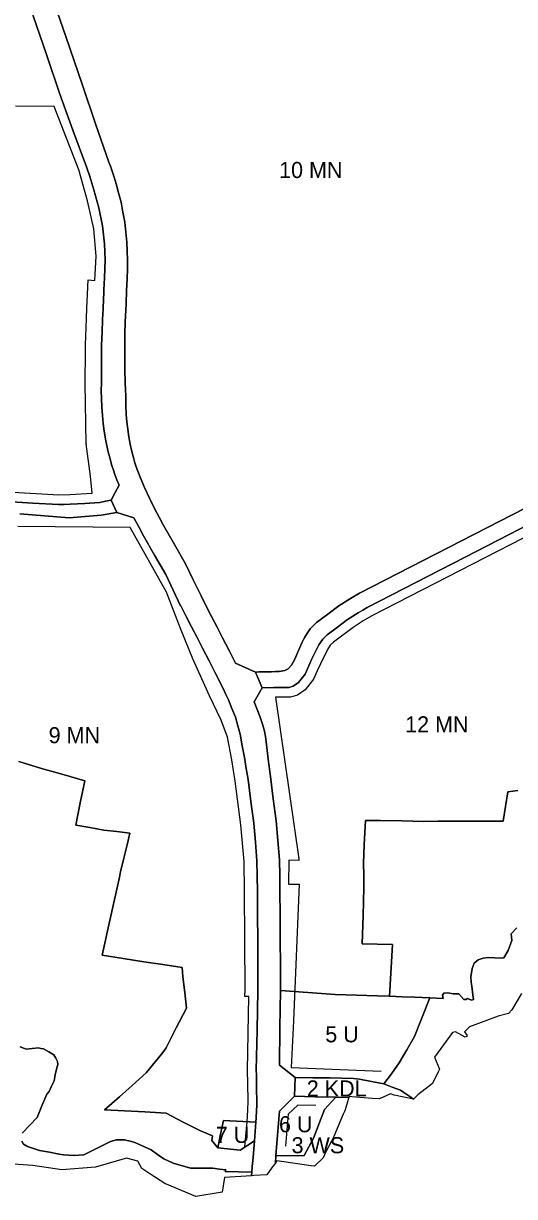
# Model space of a CAD drawing. Extents: x -294445 to -292055, y 21869 to 23693.
# Drawn here: x -293575 to -293270, y 21869 to 22598 of the extents above; entities that cross this region are included whole.
import ezdxf

# ---------------------------------------------------------------- set-up
doc = ezdxf.new("R2010")
doc.units = 0
for name, color, linetype in [('linie_rozgraniczajace', 7, 'Continuous'), ('linie_zabudowy_nieprzekraczalne', 7, 'Continuous'), ('oznaczenia_przeznaczen', 7, 'Continuous')]:
    doc.layers.add(name, color=color, linetype=linetype)

msp = doc.modelspace()

# ---------------------------------------------------------------- linework, layer by layer
at = {"layer": 'linie_rozgraniczajace'}
for points in [[(-293577.87, 22637.216), (-293574.744, 22625.222), (-293571.617, 22613.228), (-293570.297, 22608.174), (-293568.976, 22603.119), (-293560.739, 22579.011), (-293552.502, 22554.903), (-293544.186, 22532.017), (-293535.87, 22509.13), (-293533.775, 22503.209), (-293532.496, 22499.067), (-293531.216, 22494.926), (-293528.188, 22483.748), (-293525.773, 22472.607), (-293525.217, 22466.971), (-293524.661, 22461.334), (-293524.437, 22456.329), (-293524.213, 22451.323), (-293524.389, 22445.81)], [(-293461.287, 22236.143), (-293464.591, 22242.61), (-293469.372, 22252.502), (-293474.154, 22262.394), (-293481.129, 22274.51), (-293488.104, 22286.625), (-293490.691, 22291.51), (-293493.279, 22296.396), (-293496.551, 22303.171), (-293499.824, 22309.945), (-293502.409, 22316.346), (-293504.994, 22322.748), (-293505.715, 22325.192), (-293506.436, 22327.637), (-293507.531, 22332.178), (-293508.625, 22336.72), (-293509.395, 22341.445), (-293510.164, 22346.169), (-293510.605, 22350.692), (-293511.045, 22355.215), (-293511.223, 22360.983), (-293511.4, 22366.75), (-293511.555, 22370.709), (-293511.711, 22374.668), (-293511.865, 22383.437), (-293512.02, 22392.206), (-293511.995, 22395.019), (-293511.97, 22397.833), (-293511.932, 22401.583), (-293511.893, 22405.333), (-293511.641, 22412.706), (-293511.39, 22420.08), (-293511.116, 22424.28), (-293510.844, 22432.055), (-293510.573, 22439.83), (-293510.388, 22445.621), (-293510.203, 22451.413), (-293510.447, 22456.874), (-293510.692, 22462.335), (-293511.306, 22468.56), (-293511.92, 22474.784), (-293513.104, 22481.003), (-293514.288, 22487.223), (-293515.822, 22492.932), (-293517.357, 22498.642), (-293518.653, 22502.848), (-293519.95, 22507.054), (-293520.885, 22509.542), (-293521.819, 22512.029), (-293530.087, 22535.959), (-293538.354, 22559.89), (-293548.673, 22590.091), (-293558.985, 22620.268)], [(-293558.985, 22620.268), (-293548.673, 22590.091), (-293538.354, 22559.89), (-293530.087, 22535.959), (-293521.819, 22512.029), (-293520.885, 22509.542), (-293519.95, 22507.054), (-293518.653, 22502.848), (-293517.357, 22498.642), (-293515.822, 22492.932), (-293514.288, 22487.223), (-293513.104, 22481.003), (-293511.92, 22474.784), (-293511.306, 22468.56), (-293510.692, 22462.335), (-293510.447, 22456.874), (-293510.203, 22451.413), (-293510.388, 22445.621), (-293510.573, 22439.83), (-293510.844, 22432.055), (-293511.116, 22424.28), (-293511.39, 22420.08), (-293511.641, 22412.706), (-293511.893, 22405.333), (-293511.932, 22401.583), (-293511.97, 22397.833), (-293511.995, 22395.019)], [(-293447.498, 22178.015), (-293449.078, 22181.306), (-293450.657, 22184.597), (-293451.761, 22186.812), (-293452.865, 22189.027), (-293455.577, 22194.311), (-293459.618, 22202.184), (-293463.659, 22210.057), (-293467.052, 22216.678), (-293470.446, 22223.298), (-293473.752, 22229.769), (-293477.058, 22236.241), (-293477.252, 22236.381), (-293481.904, 22246.129), (-293486.556, 22255.877), (-293493.458, 22267.866), (-293500.36, 22279.854), (-293503.066, 22284.963), (-293506.251, 22291.065), (-293516.857, 22294.294), (-293520.418, 22302.027), (-293517.972, 22306.732), (-293515.525, 22311.438), (-293516.829, 22314.665), (-293518.132, 22317.893), (-293519.088, 22320.737), (-293520.043, 22323.581), (-293521.324, 22328.233), (-293522.604, 22332.885), (-293523.694, 22338.843), (-293524.784, 22344.8), (-293525.323, 22349.679), (-293525.861, 22354.558), (-293526.22, 22360.124), (-293526.557, 22370.219), (-293526.533, 22374.748), (-293526.482, 22384.564), (-293526.43, 22394.38), (-293526.4, 22398.38), (-293526.095, 22406.38), (-293525.79, 22414.38), (-293525.507, 22421.006), (-293525.401, 22423.003), (-293525.294, 22425), (-293524.93, 22432.649), (-293524.565, 22440.297), (-293524.389, 22445.81), (-293524.213, 22451.323), (-293524.437, 22456.329), (-293524.661, 22461.334), (-293525.217, 22466.971), (-293525.773, 22472.607), (-293528.188, 22483.748), (-293531.216, 22494.926), (-293532.496, 22499.067), (-293533.775, 22503.209), (-293535.87, 22509.13), (-293544.186, 22532.017), (-293552.502, 22554.903), (-293560.739, 22579.011), (-293568.976, 22603.119)], [(-293524.389, 22445.81), (-293524.565, 22440.297), (-293524.93, 22432.649), (-293525.294, 22425), (-293525.401, 22423.003), (-293525.507, 22421.006), (-293525.79, 22414.38), (-293526.095, 22406.38), (-293526.4, 22398.38), (-293526.43, 22394.38), (-293526.482, 22384.564), (-293526.533, 22374.748), (-293526.557, 22370.219), (-293526.22, 22360.124), (-293525.861, 22354.558), (-293525.323, 22349.679), (-293524.784, 22344.8), (-293523.694, 22338.843), (-293522.604, 22332.885), (-293521.324, 22328.233), (-293520.043, 22323.581), (-293519.088, 22320.737), (-293518.132, 22317.893), (-293516.829, 22314.665), (-293515.525, 22311.438), (-293517.972, 22306.732), (-293520.418, 22302.027), (-293523.989, 22301.308), (-293527.56, 22300.59), (-293536.775, 22300.015), (-293545.99, 22299.44), (-293549.595, 22299.39), (-293553.2, 22299.34), (-293569.2, 22300.225), (-293585.2, 22301.11)], [(-293511.995, 22395.019), (-293512.02, 22392.206), (-293511.865, 22383.437), (-293511.711, 22374.668), (-293511.555, 22370.709), (-293511.4, 22366.75), (-293511.223, 22360.983), (-293511.045, 22355.215), (-293510.605, 22350.692), (-293510.164, 22346.169), (-293509.395, 22341.445), (-293508.625, 22336.72), (-293507.531, 22332.178), (-293506.436, 22327.637), (-293505.715, 22325.192), (-293504.994, 22322.748), (-293502.409, 22316.346), (-293499.824, 22309.945), (-293496.551, 22303.171), (-293493.279, 22296.396), (-293490.691, 22291.51), (-293488.104, 22286.625), (-293481.129, 22274.51), (-293474.154, 22262.394), (-293469.372, 22252.502), (-293464.591, 22242.61), (-293461.287, 22236.143), (-293457.982, 22229.675), (-293454.591, 22223.059), (-293451.2, 22216.443), (-293447.179, 22208.608), (-293443.158, 22200.773), (-293430.692, 22195.192), (-293426.637, 22185.293), (-293431.464, 22176.658), (-293429.664, 22171.853), (-293427.864, 22167.047), (-293426.447, 22162.709), (-293425.03, 22158.37), (-293424.52, 22155.115), (-293424.01, 22151.86), (-293422.746, 22141.016), (-293421.482, 22130.172), (-293419.671, 22116.421), (-293417.86, 22102.67), (-293416.85, 22090.565), (-293415.84, 22078.46), (-293415.675, 22068.8), (-293415.51, 22059.14), (-293415.44, 22043.96), (-293415.37, 22028.78), (-293415.28, 22013.025), (-293415.19, 21997.27), (-293415.52, 21974.08), (-293415.85, 21950.89), (-293406, 21943.11), (-293406.443, 21931.593), (-293415.877, 21922.232), (-293416.276, 21917.222), (-293416.674, 21912.213), (-293417.457, 21902.341), (-293418.08, 21894.492), (-293418.388, 21890.053), (-293420.31, 21887.39), (-293423.69, 21882.73), (-293431.66, 21882.22), (-293433.299, 21882.115), (-293433.087, 21884.315), (-293432.753, 21887.782), (-293432.206, 21893.448), (-293431.381, 21903.848), (-293430.506, 21915.356), (-293430.343, 21918.043), (-293430.057, 21922.763), (-293429.978, 21925.797), (-293429.9, 21928.83), (-293430.02, 21935.45), (-293430.14, 21942.07), (-293430.195, 21944.945), (-293430.25, 21947.82), (-293429.72, 21972.575), (-293429.191, 21997.33), (-293429.28, 22013.019), (-293429.37, 22028.708), (-293429.44, 22043.848), (-293429.509, 22058.988), (-293429.67, 22068.373), (-293429.83, 22077.758), (-293430.807, 22089.465), (-293431.784, 22101.173), (-293433.58, 22114.81), (-293435.376, 22128.448), (-293436.44, 22135.282), (-293437.504, 22142.116), (-293438.922, 22149.323), (-293440.34, 22156.53), (-293441.76, 22161.825), (-293443.18, 22167.12), (-293445.339, 22172.567), (-293447.498, 22178.015)], [(-293239.368, 22309.206), (-293302.714, 22276.673), (-293366.06, 22244.14), (-293371.586, 22240.965), (-293378.858, 22236.241), (-293385.839, 22231.085), (-293392.82, 22225.929), (-293394.785, 22223.98), (-293396.75, 22222.032), (-293398.428, 22219.484), (-293400.105, 22216.935), (-293400.896, 22215.39), (-293401.686, 22213.845), (-293404.005, 22208.53), (-293406.323, 22203.215), (-293407.359, 22201.348), (-293408.395, 22199.482), (-293410.375, 22197.1), (-293412.577, 22196.212), (-293415.968, 22195.603), (-293418.249, 22195.517), (-293420.753, 22195.422), (-293423.701, 22195.372), (-293426.65, 22195.323), (-293428.671, 22195.257), (-293430.692, 22195.192), (-293443.158, 22200.773), (-293447.179, 22208.608), (-293451.2, 22216.443), (-293454.591, 22223.059), (-293457.982, 22229.675), (-293461.287, 22236.143)], [(-293430.692, 22195.192), (-293428.671, 22195.257), (-293426.65, 22195.323), (-293423.701, 22195.372), (-293420.753, 22195.422), (-293418.249, 22195.517), (-293415.968, 22195.603), (-293412.577, 22196.212), (-293410.375, 22197.1), (-293408.395, 22199.482), (-293407.359, 22201.348), (-293406.323, 22203.215), (-293404.005, 22208.53), (-293401.686, 22213.845), (-293400.896, 22215.39), (-293400.105, 22216.935), (-293398.428, 22219.484), (-293396.75, 22222.032), (-293394.785, 22223.98), (-293392.82, 22225.929), (-293385.839, 22231.085), (-293378.858, 22236.241), (-293371.586, 22240.965), (-293366.06, 22244.14), (-293302.714, 22276.673), (-293239.368, 22309.206)], [(-293585.2, 22301.11), (-293569.2, 22300.225), (-293553.2, 22299.34), (-293549.595, 22299.39), (-293545.99, 22299.44), (-293536.775, 22300.015), (-293527.56, 22300.59), (-293523.989, 22301.308), (-293520.418, 22302.027), (-293516.857, 22294.294), (-293526.67, 22292.75), (-293536.565, 22291.925), (-293546.46, 22291.1), (-293561.8, 22292.265), (-293577.14, 22293.43)], [(-293267.58, 22121.58), (-293270.775, 22121.14), (-293273.97, 22120.7), (-293275.353, 22111.558), (-293276.735, 22102.415), (-293278.559, 22102.424), (-293285.604, 22102.457), (-293292.65, 22102.49), (-293300.55, 22102.525), (-293308.45, 22102.56), (-293317.375, 22102.48), (-293326.3, 22102.4), (-293339.65, 22102.625), (-293353, 22102.85), (-293357.695, 22102.93), (-293362.39, 22103.01), (-293362.576, 22099.187), (-293363.133, 22087.764), (-293363.69, 22076.34), (-293363.485, 22068.795), (-293363.28, 22061.25), (-293363.835, 22043.81), (-293364.39, 22026.37), (-293345.484, 22025.806), (-293347.351, 21993.692), (-293354.9, 21993.94), (-293368.005, 21994.37), (-293381.11, 21994.8), (-293398.15, 21996.035), (-293415.19, 21997.27), (-293415.28, 22013.025), (-293415.37, 22028.78), (-293415.44, 22043.96), (-293415.51, 22059.14), (-293415.675, 22068.8), (-293415.84, 22078.46), (-293416.85, 22090.565), (-293417.86, 22102.67), (-293419.671, 22116.421), (-293421.482, 22130.172), (-293422.746, 22141.016), (-293424.01, 22151.86), (-293424.52, 22155.115), (-293425.03, 22158.37), (-293426.447, 22162.709), (-293427.864, 22167.047), (-293429.664, 22171.853), (-293431.464, 22176.658), (-293426.637, 22185.293), (-293419.288, 22185.5), (-293414.598, 22185.512), (-293409.908, 22185.524), (-293407.28, 22186.34), (-293403.95, 22188.59), (-293399.77, 22193.87), (-293396.863, 22200.588), (-293395.827, 22202.922), (-293393.542, 22207.556), (-293391.257, 22212.19), (-293388.97, 22215.664), (-293386.221, 22218.391), (-293379.84, 22223.114), (-293373.459, 22227.837), (-293370.151, 22229.957), (-293366.843, 22232.077), (-293364.105, 22233.693), (-293361.368, 22235.308), (-293300.311, 22266.665), (-293239.255, 22298.022)], [(-293239.255, 22298.022), (-293300.311, 22266.665), (-293361.368, 22235.308), (-293364.105, 22233.693), (-293366.843, 22232.077), (-293370.151, 22229.957), (-293373.459, 22227.837), (-293379.84, 22223.114), (-293386.221, 22218.391), (-293388.97, 22215.664), (-293391.257, 22212.19), (-293393.542, 22207.556), (-293395.827, 22202.922), (-293396.863, 22200.588), (-293399.77, 22193.87), (-293403.95, 22188.59), (-293407.28, 22186.34), (-293409.908, 22185.524), (-293414.598, 22185.512), (-293419.288, 22185.5), (-293426.637, 22185.293), (-293430.692, 22195.192)], [(-293577.14, 22293.43), (-293561.8, 22292.265), (-293546.46, 22291.1), (-293536.565, 22291.925), (-293526.67, 22292.75), (-293516.857, 22294.294), (-293506.251, 22291.065), (-293503.066, 22284.963), (-293500.36, 22279.854), (-293493.458, 22267.866), (-293486.556, 22255.877), (-293481.904, 22246.129), (-293477.252, 22236.381), (-293477.058, 22236.241), (-293473.752, 22229.769), (-293470.446, 22223.298), (-293467.052, 22216.678), (-293463.659, 22210.057), (-293459.618, 22202.184), (-293455.577, 22194.311), (-293452.865, 22189.027), (-293451.761, 22186.812), (-293450.657, 22184.597), (-293449.078, 22181.306), (-293447.498, 22178.015), (-293445.339, 22172.567), (-293443.18, 22167.12), (-293441.76, 22161.825), (-293440.34, 22156.53), (-293438.922, 22149.323), (-293437.504, 22142.116), (-293436.44, 22135.282), (-293435.376, 22128.448), (-293433.58, 22114.81), (-293431.784, 22101.173), (-293430.807, 22089.465), (-293429.83, 22077.758), (-293429.67, 22068.373), (-293429.509, 22058.988), (-293429.44, 22043.848), (-293429.37, 22028.708), (-293429.28, 22013.019), (-293429.191, 21997.33), (-293429.72, 21972.575), (-293430.25, 21947.82), (-293430.195, 21944.945), (-293430.14, 21942.07), (-293430.02, 21935.45), (-293429.9, 21928.83), (-293429.978, 21925.797), (-293430.057, 21922.763), (-293430.343, 21918.043), (-293430.506, 21915.356), (-293450.571, 21916.441), (-293452.39, 21907.935), (-293454.21, 21899.43), (-293457.97, 21904.02), (-293457.509, 21906.887), (-293464.981, 21910.031), (-293475.662, 21915.48), (-293486.343, 21920.929), (-293499.585, 21921.866), (-293512.071, 21922.457), (-293524.556, 21923.047), (-293519.958, 21927.134), (-293515.36, 21931.221), (-293511.424, 21934.719), (-293507.487, 21938.218), (-293503.081, 21942.133), (-293498.675, 21946.049), (-293493.918, 21951.858), (-293489.161, 21957.667)], [(-293489.161, 21957.667), (-293487.679, 21959.611), (-293486.197, 21961.555), (-293479.942, 21973.967), (-293473.687, 21986.379), (-293474.75, 21996.073), (-293475.812, 22005.768), (-293476.05, 22008.634), (-293476.288, 22011.499), (-293488.234, 22013.34), (-293500.18, 22015.18), (-293513.07, 22017.16), (-293525.96, 22019.14), (-293524.34, 22026.715), (-293522.72, 22034.29), (-293519.625, 22048.25), (-293516.53, 22062.21), (-293515.555, 22066.605), (-293514.58, 22071), (-293512.584, 22079.414), (-293510.588, 22087.828), (-293508.8, 22094.99), (-293516.88, 22095.995), (-293524.96, 22097), (-293533.7, 22098.505), (-293542.44, 22100.01), (-293539.65, 22113.815), (-293536.86, 22127.62), (-293550.27, 22131.455), (-293563.68, 22135.29), (-293577.79, 22139.63)], [(-293577.79, 22139.63), (-293563.68, 22135.29), (-293550.27, 22131.455), (-293536.86, 22127.62), (-293539.65, 22113.815), (-293542.44, 22100.01), (-293533.7, 22098.505), (-293524.96, 22097), (-293516.88, 22095.995), (-293508.8, 22094.99), (-293510.588, 22087.828), (-293512.584, 22079.414), (-293514.58, 22071), (-293515.555, 22066.605), (-293516.53, 22062.21), (-293519.625, 22048.25), (-293522.72, 22034.29), (-293524.34, 22026.715), (-293525.96, 22019.14), (-293513.07, 22017.16), (-293500.18, 22015.18), (-293488.234, 22013.34), (-293476.288, 22011.499), (-293476.05, 22008.634), (-293475.812, 22005.768), (-293474.75, 21996.073), (-293473.687, 21986.379), (-293479.942, 21973.967), (-293486.197, 21961.555), (-293487.679, 21959.611), (-293489.161, 21957.667), (-293493.918, 21951.858), (-293498.675, 21946.049), (-293503.081, 21942.133), (-293507.487, 21938.218), (-293511.424, 21934.719), (-293515.36, 21931.221), (-293519.958, 21927.134), (-293524.556, 21923.047), (-293512.071, 21922.457), (-293499.585, 21921.866), (-293486.343, 21920.929), (-293475.662, 21915.48), (-293464.981, 21910.031), (-293457.509, 21906.887), (-293457.97, 21904.02), (-293454.21, 21899.43), (-293440.302, 21898.099), (-293431.381, 21903.848), (-293432.206, 21893.448), (-293432.753, 21887.782), (-293433.087, 21884.315), (-293449.51, 21884.67), (-293449.08, 21885.78), (-293453.18, 21886.295), (-293457.28, 21886.81), (-293464.24, 21886.82), (-293471.2, 21886.83), (-293481.878, 21889.943), (-293487.64, 21892.55), (-293491.615, 21895.355), (-293495.59, 21898.16), (-293499.72, 21900.115), (-293503.85, 21902.07), (-293505.795, 21902.745), (-293507.74, 21903.42), (-293512.12, 21904.39), (-293517.14, 21904.42), (-293520.76, 21903.34), (-293529.075, 21899.205), (-293537.39, 21895.07), (-293540.465, 21894.875), (-293543.54, 21894.68), (-293546.835, 21894.915), (-293550.13, 21895.15), (-293552.84, 21895.6), (-293558.87, 21896.76), (-293564.9, 21897.92), (-293568.685, 21899.145), (-293572.47, 21900.37), (-293574.85, 21901.66), (-293575.88, 21903.54)], [(-293364.39, 22026.37), (-293363.835, 22043.81), (-293363.28, 22061.25), (-293363.485, 22068.795), (-293363.69, 22076.34), (-293363.133, 22087.764), (-293362.576, 22099.187), (-293362.39, 22103.01), (-293357.695, 22102.93), (-293353, 22102.85), (-293339.65, 22102.625), (-293326.3, 22102.4), (-293317.375, 22102.48), (-293308.45, 22102.56), (-293300.55, 22102.525), (-293292.65, 22102.49), (-293285.604, 22102.457), (-293278.559, 22102.424), (-293276.735, 22102.415), (-293275.353, 22111.558), (-293273.97, 22120.7), (-293270.775, 22121.14), (-293267.58, 22121.58)], [(-293268.31, 22036.13), (-293271.88, 22032.42), (-293271.39, 22028.43), (-293273.69, 22022.1), (-293276.417, 22017.468), (-293277.732, 22017.303), (-293281.947, 22017.504), (-293286.162, 22017.705), (-293289.19, 22017.3), (-293292.28, 22016.41), (-293294.71, 22014.29), (-293296.1, 22010.98), (-293296.83, 22005.66), (-293296.57, 22002.53), (-293296.24, 22000), (-293295.55, 21994.65), (-293295.24, 21991.76), (-293296.52, 21991.19), (-293298.87, 21992.34), (-293299.99, 21991.66), (-293301.14, 21991.58), (-293304.24, 21995.26), (-293307.77, 21995.28), (-293311.1, 21995.9), (-293313.55, 21995.53), (-293314.48, 21994.29), (-293314.05, 21992.23), (-293322.43, 21992.67), (-293327.138, 21992.865), (-293331.846, 21993.06), (-293339.598, 21993.376), (-293347.351, 21993.692), (-293345.484, 22025.806), (-293364.39, 22026.37)], [(-293350.95, 21939.18), (-293346.285, 21945.551), (-293341.41, 21952.21), (-293336.7, 21960.42), (-293331.99, 21968.63), (-293327.993, 21978.682), (-293322.43, 21992.67), (-293314.05, 21992.23), (-293314.48, 21994.29), (-293313.55, 21995.53), (-293311.1, 21995.9), (-293307.77, 21995.28), (-293304.24, 21995.26), (-293301.14, 21991.58), (-293299.99, 21991.66), (-293298.87, 21992.34), (-293296.52, 21991.19), (-293295.24, 21991.76), (-293295.55, 21994.65), (-293296.24, 22000), (-293296.57, 22002.53), (-293296.83, 22005.66), (-293296.1, 22010.98), (-293294.71, 22014.29), (-293292.28, 22016.41), (-293289.19, 22017.3), (-293286.162, 22017.705), (-293281.947, 22017.504), (-293277.732, 22017.303), (-293276.417, 22017.468), (-293273.69, 22022.1), (-293271.39, 22028.43), (-293271.88, 22032.42), (-293268.31, 22036.13)], [(-293265.33, 21995.34), (-293271.48, 21985.26), (-293273.51, 21983), (-293279.94, 21981.29), (-293297.75, 21974.6), (-293300.77, 21971.67), (-293299.13, 21969.29), (-293299.59, 21968.7), (-293300.42, 21968.34), (-293306.34, 21971.65), (-293308.36, 21971.25), (-293319.55, 21955.9), (-293316.28, 21948.43), (-293316.94, 21947.1), (-293320.69, 21939.54), (-293329.88, 21932.43), (-293332.49, 21929.81), (-293334.76, 21931.337), (-293338.493, 21933.848), (-293340.568, 21935.244), (-293345.76, 21937.213), (-293350.95, 21939.18)], [(-293575.67, 21908.57), (-293571.085, 21913.48), (-293566.5, 21918.39), (-293563.495, 21925.645), (-293560.49, 21932.9), (-293559.04, 21934.45), (-293557.49, 21937.78), (-293555.94, 21941.11), (-293555.21, 21944.785), (-293554.48, 21948.46), (-293554.015, 21949.84), (-293553.55, 21951.22), (-293553.84, 21953.23), (-293554.91, 21955.25), (-293555.98, 21957.27), (-293559.225, 21959.14), (-293562.47, 21961.01), (-293564.09, 21961.29), (-293565.71, 21961.57), (-293569.47, 21961.175), (-293573.23, 21960.78), (-293577.04, 21962.265)], [(-293577.04, 21962.265), (-293573.23, 21960.78), (-293569.47, 21961.175), (-293565.71, 21961.57), (-293564.09, 21961.29), (-293562.47, 21961.01), (-293559.225, 21959.14), (-293555.98, 21957.27), (-293554.91, 21955.25), (-293553.84, 21953.23), (-293553.55, 21951.22), (-293554.015, 21949.84), (-293554.48, 21948.46), (-293555.21, 21944.785), (-293555.94, 21941.11), (-293557.49, 21937.78), (-293559.04, 21934.45), (-293560.49, 21932.9), (-293563.495, 21925.645), (-293566.5, 21918.39), (-293571.085, 21913.48), (-293575.67, 21908.57)], [(-293543.54, 21894.68), (-293540.465, 21894.875), (-293537.39, 21895.07), (-293529.075, 21899.205), (-293520.76, 21903.34), (-293517.14, 21904.42), (-293512.12, 21904.39), (-293507.74, 21903.42), (-293505.795, 21902.745), (-293503.85, 21902.07), (-293499.72, 21900.115), (-293495.59, 21898.16), (-293491.615, 21895.355), (-293487.64, 21892.55), (-293481.878, 21889.943), (-293471.2, 21886.83), (-293464.24, 21886.82), (-293457.28, 21886.81), (-293453.18, 21886.295), (-293449.08, 21885.78), (-293449.51, 21884.67), (-293433.087, 21884.315), (-293433.299, 21882.115), (-293450.05, 21881.04), (-293451.42, 21871.91), (-293467.83, 21869.21), (-293487.13, 21877.38), (-293496.31, 21883.41), (-293501.28, 21886.54), (-293503.78, 21891.18), (-293511, 21893.09), (-293530.1, 21887.37), (-293551.15, 21885.72), (-293569.14, 21888.5), (-293587.42, 21889.69)], [(-293575.88, 21903.54), (-293574.85, 21901.66), (-293572.47, 21900.37), (-293568.685, 21899.145), (-293564.9, 21897.92), (-293558.87, 21896.76), (-293552.84, 21895.6), (-293550.13, 21895.15), (-293546.835, 21894.915), (-293543.54, 21894.68)]]:
    msp.add_lwpolyline(points, dxfattribs=at)
for points in [[(-293415.85, 21950.89), (-293415.52, 21974.08), (-293415.19, 21997.27), (-293398.15, 21996.035), (-293381.11, 21994.8), (-293368.005, 21994.37), (-293354.9, 21993.94), (-293347.351, 21993.692), (-293339.598, 21993.376), (-293331.846, 21993.06), (-293327.138, 21992.865), (-293322.43, 21992.67), (-293327.993, 21978.682), (-293331.99, 21968.63), (-293336.7, 21960.42), (-293341.41, 21952.21), (-293346.285, 21945.551), (-293350.95, 21939.18), (-293358.535, 21940.685), (-293366.12, 21942.19), (-293367.965, 21942.4), (-293369.81, 21942.61), (-293377.05, 21942.825), (-293384.29, 21943.04), (-293395.145, 21943.075), (-293406, 21943.11)], [(-293406.443, 21931.593), (-293406, 21943.11), (-293395.145, 21943.075), (-293384.29, 21943.04), (-293377.05, 21942.825), (-293369.81, 21942.61), (-293367.965, 21942.4), (-293366.12, 21942.19), (-293358.535, 21940.685), (-293350.95, 21939.18), (-293345.76, 21937.213), (-293340.568, 21935.244), (-293338.493, 21933.848), (-293334.76, 21931.337), (-293332.49, 21929.81), (-293344.62, 21932.14), (-293346.83, 21933.12), (-293353.56, 21929.85), (-293358.16, 21930.1), (-293370.74, 21931.19), (-293372.57, 21931.31), (-293372.754, 21930.692), (-293380.863, 21930.933), (-293393.653, 21931.263)], [(-293418.388, 21890.053), (-293418.08, 21894.492), (-293400.532, 21894.668), (-293394.588, 21905.548), (-293387.731, 21923.286), (-293380.863, 21930.933), (-293372.754, 21930.692), (-293373.12, 21929.46), (-293375.02, 21923.13), (-293375.49, 21922.04), (-293376.18, 21920.41), (-293382.12, 21906.58), (-293383.57, 21903.67), (-293386.92, 21896.96), (-293388.76, 21893.26), (-293394.03, 21888), (-293396.31, 21888.32), (-293404.61, 21889.49), (-293417.48, 21891.31)], [(-293418.08, 21894.492), (-293417.457, 21902.341), (-293416.674, 21912.213), (-293416.276, 21917.222), (-293415.877, 21922.232), (-293406.443, 21931.593), (-293393.653, 21931.263), (-293380.863, 21930.933), (-293387.731, 21923.286), (-293394.588, 21905.548), (-293400.532, 21894.668)], [(-293454.21, 21899.43), (-293452.39, 21907.935), (-293450.571, 21916.441), (-293430.506, 21915.356), (-293431.381, 21903.848), (-293440.302, 21898.099)]]:
    msp.add_lwpolyline(points, close=True, dxfattribs=at)
at = {"layer": 'linie_zabudowy_nieprzekraczalne'}
for points in [[(-293584.837, 22307.099), (-293553.076, 22305.342), (-293546.219, 22305.437), (-293532.338, 22306.304), (-293532.338, 22306.304), (-293533.218, 22316.915), (-293536.051, 22336.965), (-293536.051, 22336.965), (-293536.051, 22336.965), (-293536.021, 22336.755), (-293536.051, 22336.965), (-293536.533, 22374.8), (-293536.43, 22394.444), (-293536.399, 22398.608), (-293535.782, 22414.784), (-293535.496, 22421.485), (-293535.282, 22425.505), (-293534.636, 22439.037), (-293530.636, 22438.616), (-293529.747, 22453.702), (-293531.141, 22470.663), (-293535.073, 22488.081), (-293535.073, 22488.081), (-293535.073, 22488.081), (-293540.44, 22507.24), (-293555.782, 22546.61), (-293555.782, 22546.61), (-293579.925, 22546.851)], [(-293241.307, 22290.223), (-293358.47, 22230.051), (-293363.698, 22226.966), (-293370.052, 22222.894), (-293382.303, 22213.826), (-293384.302, 22211.843), (-293386.041, 22209.202), (-293390.392, 22200.377), (-293392.397, 22195.86), (-293394.567, 22190.775), (-293399.822, 22184.138), (-293404.655, 22180.872), (-293408.99, 22179.527), (-293418.236, 22179.563), (-293418.236, 22179.563), (-293418.236, 22179.563), (-293418.236, 22179.563), (-293403.849, 22079.062), (-293403.849, 22079.062), (-293403.849, 22079.062), (-293403.849, 22079.062), (-293403.846, 22077.972), (-293410.05, 22078.224), (-293410.311, 22063.433), (-293403.634, 22063.334), (-293403.634, 22063.334), (-293407.195, 21978.331), (-293407.195, 21978.331), (-293408.48, 21949.358), (-293352.636, 21947.033)], [(-293437.265, 21900.056), (-293435.988, 21915.652), (-293435.462, 21922.879), (-293435.356, 21928.747), (-293435.489, 21939.286), (-293435.641, 21947.829), (-293434.863, 21993.51), (-293437.273, 21993.579), (-293437.191, 21997.392), (-293437.37, 22028.666), (-293437.509, 22058.901), (-293437.824, 22077.356), (-293439.74, 22100.318), (-293443.295, 22127.31), (-293445.384, 22140.728), (-293448.137, 22154.72), (-293452.076, 22165.259), (-293459.326, 22180.357), (-293469.578, 22203.421), (-293477.367, 22222.329), (-293477.367, 22222.329), (-293477.367, 22222.329), (-293486.034, 22244.841), (-293486.034, 22244.841), (-293508.701, 22285.12), (-293508.701, 22285.12), (-293578.4, 22285.62)], [(-293393.201, 21925.776), (-293404.486, 21926.006), (-293410.5, 21920.317), (-293412.051, 21900.553)]]:
    msp.add_lwpolyline(points, dxfattribs=at)

# ---------------------------------------------------------------- texts
at = {"layer": 'oznaczenia_przeznaczen'}
for s, p in [('10 MN', (-293416.048, 22502.228)), ('12 MN', (-293337.689, 22157.681)), ('9 MN', (-293559.288, 22150.947)), ('5 U', (-293387.343, 21965.064)), ('2 KDL', (-293398.845, 21931.401)), ('6 U', (-293416.114, 21909.147)), ('7 U', (-293455.412, 21902.535)), ('3 WS', (-293408.281, 21896.096))]:
    msp.add_text(s, height=10, dxfattribs=at).set_placement(p)

doc.saveas('drawing.dxf')
